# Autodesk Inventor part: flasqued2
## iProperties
Shininess: 21.0
Length Units: 11269
Angle Units: 11279
Time Units: 11290
Mass Units: 11283
Length Display Precision: 3
Angle Display Precision: 2
Compacted: True
Created: 2001-12
Part Number: flasqued2
Material: Par défaut
Document SubType Name: Tôlerie
Designer: pichon
Density: 0.0
Volumn: 0.0
Area: 0.0
PropertySet Name: Model Information
Control State: 0
Master: False
Checked Out: False
Author: pichon
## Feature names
1. Arrondi de coin1
2. Extrusion1
3. Extrusion5
4. Congé2 [Fillet]
5. Extrusion6
6. Plaque1
7. Plaque2
8. Pli1
9. Plaque3
10. Pli2
